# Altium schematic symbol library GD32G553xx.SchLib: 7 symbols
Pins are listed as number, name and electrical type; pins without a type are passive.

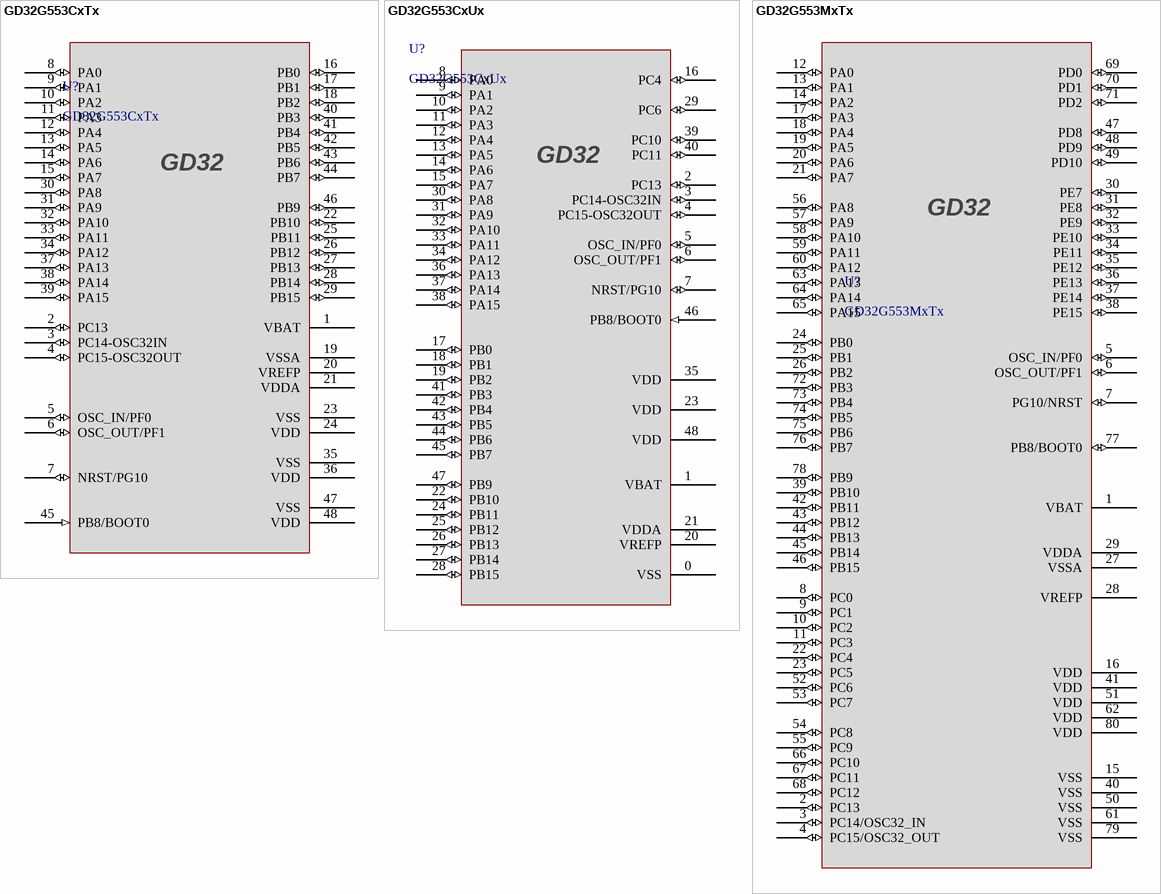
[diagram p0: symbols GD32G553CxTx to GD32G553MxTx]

## GD32G553CxTx
designator U?
footprint LQFP48_7x7x1.6
pins: 1 VBAT (power), 2 PC13 (io), 3 PC14-OSC32IN (io), 4 PC15-OSC32OUT (io), 5 OSC_IN/PF0 (io), 6 OSC_OUT/PF1 (io), 7 NRST/PG10 (io), 8 PA0 (io), 9 PA1 (io), 10 PA2 (io), 11 PA3 (io), 12 PA4 (io), 13 PA5 (io), 14 PA6 (io), 15 PA7 (io), 16 PB0 (io), 17 PB1 (io), 18 PB2 (io), 19 VSSA (power), 20 VREFP (power), 21 VDDA (power), 22 PB10 (io), 23 VSS (power), 24 VDD (power), 25 PB11 (io), 26 PB12 (io), 27 PB13 (io), 28 PB14 (io), 29 PB15 (io), 30 PA8 (io), 31 PA9 (io), 32 PA10 (io), 33 PA11 (io), 34 PA12 (io), 35 VSS (power), 36 VDD (power), 37 PA13 (io), 38 PA14 (io), 39 PA15 (io), 40 PB3 (io), 41 PB4 (io), 42 PB5 (io), 43 PB6 (io), 44 PB7 (io), 45 PB8/BOOT0 (in), 46 PB9 (io), 47 VSS (power), 48 VDD (power)

## GD32G553CxUx
designator U?
footprint QFN48_7X7X0.6
pins: 0 VSS (power), 1 VBAT (power), 2 PC13 (io), 3 PC14-OSC32IN (io), 4 PC15-OSC32OUT (io), 5 OSC_IN/PF0 (io), 6 OSC_OUT/PF1 (io), 7 NRST/PG10 (io), 8 PA0 (io), 9 PA1 (io), 10 PA2 (io), 11 PA3 (io), 12 PA4 (io), 13 PA5 (io), 14 PA6 (io), 15 PA7 (io), 16 PC4 (io), 17 PB0 (io), 18 PB1 (io), 19 PB2 (io), 20 VREFP (power), 21 VDDA (power), 22 PB10 (io), 23 VDD (power), 24 PB11 (io), 25 PB12 (io), 26 PB13 (io), 27 PB14 (io), 28 PB15 (io), 29 PC6 (io), 30 PA8 (io), 31 PA9 (io), 32 PA10 (io), 33 PA11 (io), 34 PA12 (io), 35 VDD (power), 36 PA13 (io), 37 PA14 (io), 38 PA15 (io), 39 PC10 (io), 40 PC11 (io), 41 PB3 (io), 42 PB4 (io), 43 PB5 (io), 44 PB6 (io), 45 PB7 (io), 46 PB8/BOOT0 (in), 47 PB9 (io), 48 VDD (power)

## GD32G553MxTx
designator U?
footprint LQFP80_12x12x1.6
pins: 1 VBAT (power), 2 PC13 (io), 3 PC14/OSC32_IN (io), 4 PC15/OSC32_OUT (io), 5 OSC_IN/PF0 (io), 6 OSC_OUT/PF1 (io), 7 PG10/NRST (io), 8 PC0 (io), 9 PC1 (io), 10 PC2 (io), 11 PC3 (io), 12 PA0 (io), 13 PA1 (io), 14 PA2 (io), 15 VSS (power), 16 VDD (power), 17 PA3 (io), 18 PA4 (io), 19 PA5 (io), 20 PA6 (io), 21 PA7 (io), 22 PC4 (io), 23 PC5 (io), 24 PB0 (io), 25 PB1 (io), 26 PB2 (io), 27 VSSA (power), 28 VREFP (power), 29 VDDA (power), 30 PE7 (io), 31 PE8 (io), 32 PE9 (io), 33 PE10 (io), 34 PE11 (io), 35 PE12 (io), 36 PE13 (io), 37 PE14 (io), 38 PE15 (io), 39 PB10 (io), 40 VSS (power), 41 VDD (power), 42 PB11 (io), 43 PB12 (io), 44 PB13 (io), 45 PB14 (io), 46 PB15 (io), 47 PD8 (io), 48 PD9 (io), 49 PD10 (io), 50 VSS (power), 51 VDD (power), 52 PC6 (io), 53 PC7 (io), 54 PC8 (io), 55 PC9 (io), 56 PA8 (io), 57 PA9 (io), 58 PA10 (io), 59 PA11 (io), 60 PA12 (io), 61 VSS (power), 62 VDD (power), 63 PA13 (io), 64 PA14 (io), 65 PA15 (io), 66 PC10 (io), 67 PC11 (io), 68 PC12 (io), 69 PD0 (io), 70 PD1 (io), 71 PD2 (io), 72 PB3 (io), 73 PB4 (io), 74 PB5 (io), 75 PB6 (io), 76 PB7 (io), 77 PB8/BOOT0 (io), 78 PB9 (io), 79 VSS (power), 80 VDD (power)

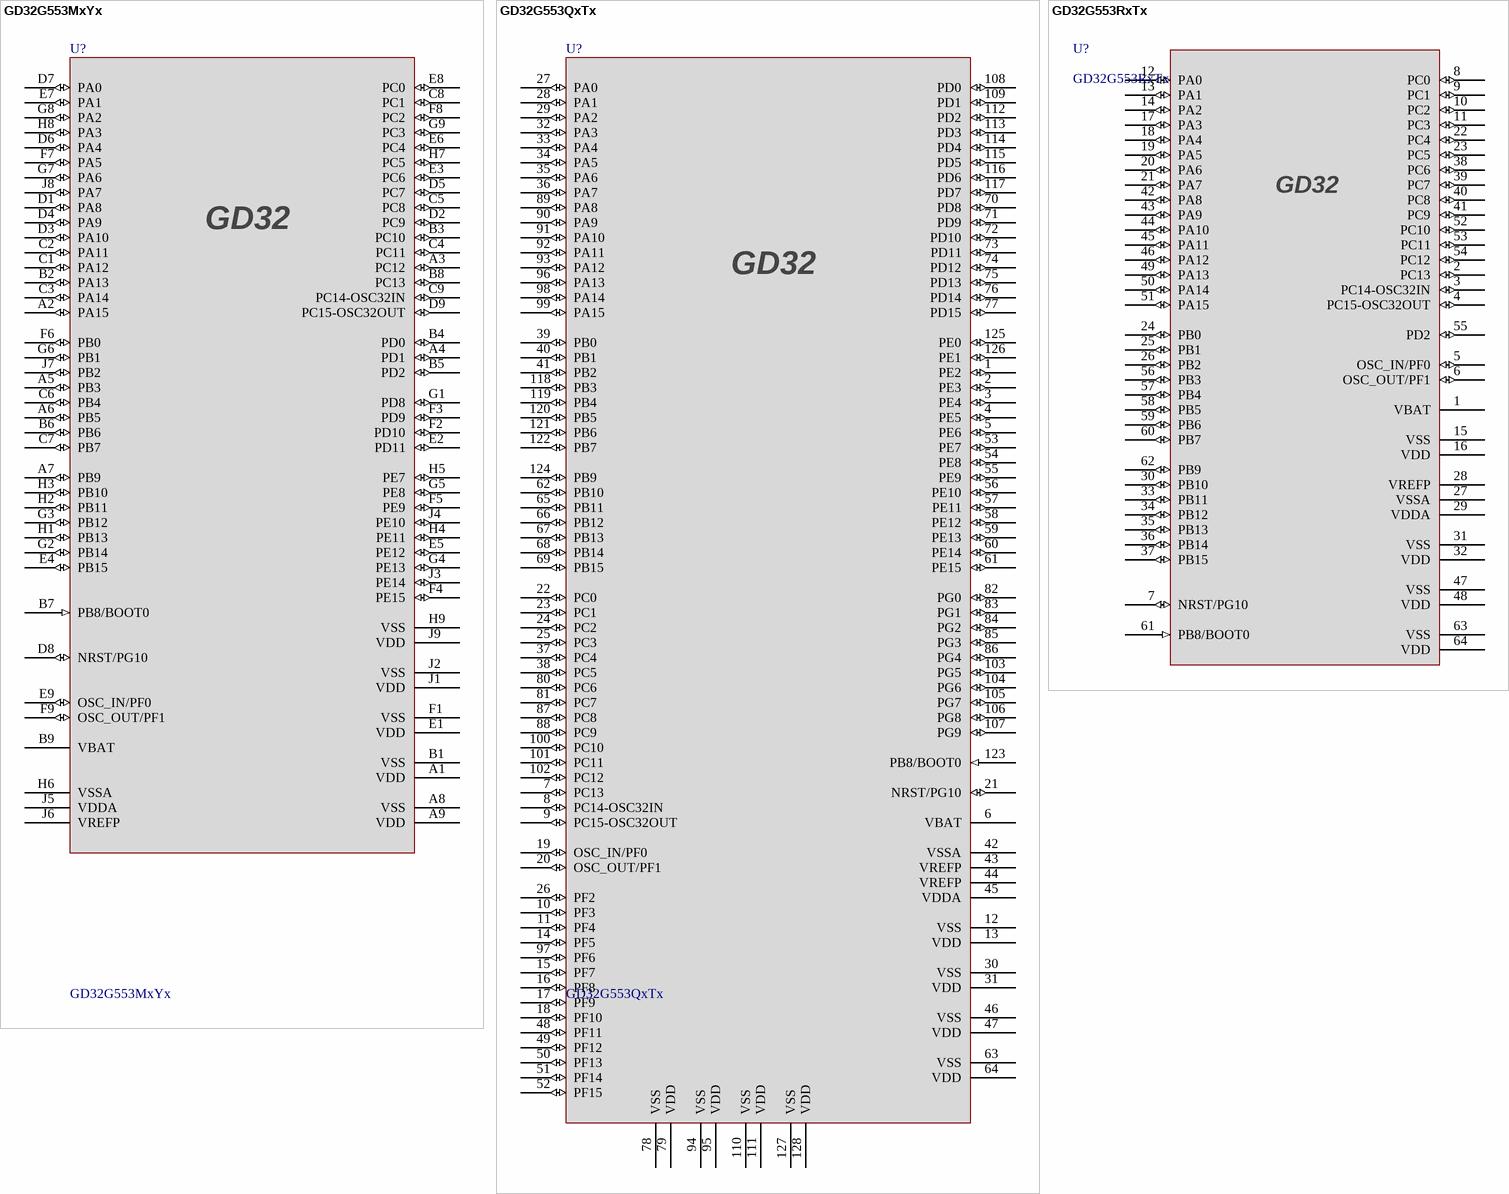
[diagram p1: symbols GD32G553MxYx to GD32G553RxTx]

## GD32G553MxYx
designator U?
footprint WLCSP81_4x4x0.58
pins: A1 VDD (power), A2 PA15 (io), A3 PC12 (io), A4 PD1 (io), A5 PB3 (io), A6 PB5 (io), A7 PB9 (io), A8 VSS (power), A9 VDD (power), B1 VSS (power), B2 PA13 (io), B3 PC10 (io), B4 PD0 (io), B5 PD2 (io), B6 PB6 (io), B7 PB8/BOOT0 (in), B8 PC13 (io), B9 VBAT (power), C1 PA12 (io), C2 PA11 (io), C3 PA14 (io), C4 PC11 (io), C5 PC8 (io), C6 PB4 (io), C7 PB7 (io), C8 PC1 (io), C9 PC14-OSC32IN (io), D1 PA8 (io), D2 PC9 (io), D3 PA10 (io), D4 PA9 (io), D5 PC7 (io), D6 PA4 (io), D7 PA0 (io), D8 NRST/PG10 (io), D9 PC15-OSC32OUT (io), E1 VDD (power), E2 PD11 (io), E3 PC6 (io), E4 PB15 (io), E5 PE12 (io), E6 PC4 (io), E7 PA1 (io), E8 PC0 (io), E9 OSC_IN/PF0 (io), F1 VSS (power), F2 PD10 (io), F3 PD9 (io), F4 PE15 (io), F5 PE9 (io), F6 PB0 (io), F7 PA5 (io), F8 PC2 (io), F9 OSC_OUT/PF1 (io), G1 PD8 (io), G2 PB14 (io), G3 PB12 (io), G4 PE13 (io), G5 PE8 (io), G6 PB1 (io), G7 PA6 (io), G8 PA2 (io), G9 PC3 (io), H1 PB13 (io), H2 PB11 (io), H3 PB10 (io), H4 PE11 (io), H5 PE7 (io), H6 VSSA (power), H7 PC5 (io), H8 PA3 (io), H9 VSS (power), J1 VDD (power), J2 VSS (power), J3 PE14 (io), J4 PE10 (io), J5 VDDA (power), J6 VREFP (power), J7 PB2 (io), J8 PA7 (io), J9 VDD (power)
2 alternate drawings of the same symbol

## GD32G553QxTx
designator U?
footprint LQFP128_14X14X1.6
pins: 1 PE2 (io), 2 PE3 (io), 3 PE4 (io), 4 PE5 (io), 5 PE6 (io), 6 VBAT (power), 7 PC13 (io), 8 PC14-OSC32IN (io), 9 PC15-OSC32OUT (io), 10 PF3 (io), 11 PF4 (io), 12 VSS (power), 13 VDD (power), 14 PF5 (io), 15 PF7 (io), 16 PF8 (io), 17 PF9 (io), 18 PF10 (io), 19 OSC_IN/PF0 (io), 20 OSC_OUT/PF1 (io), 21 NRST/PG10 (io), 22 PC0 (io), 23 PC1 (io), 24 PC2 (io), 25 PC3 (io), 26 PF2 (io), 27 PA0 (io), 28 PA1 (io), 29 PA2 (io), 30 VSS (power), 31 VDD (power), 32 PA3 (io), 33 PA4 (io), 34 PA5 (io), 35 PA6 (io), 36 PA7 (io), 37 PC4 (io), 38 PC5 (io), 39 PB0 (io), 40 PB1 (io), 41 PB2 (io), 42 VSSA (power), 43 VREFP (power), 44 VREFP (power), 45 VDDA (power), 46 VSS (power), 47 VDD (power), 48 PF11 (io), 49 PF12 (io), 50 PF13 (io), 51 PF14 (io), 52 PF15 (io), 53 PE7 (io), 54 PE8 (io), 55 PE9 (io), 56 PE10 (io), 57 PE11 (io), 58 PE12 (io), 59 PE13 (io), 60 PE14 (io), 61 PE15 (io), 62 PB10 (io), 63 VSS (power), 64 VDD (power), 65 PB11 (io), 66 PB12 (io), 67 PB13 (io), 68 PB14 (io), 69 PB15 (io), 70 PD8 (io), 71 PD9 (io), 72 PD10 (io), 73 PD11 (io), 74 PD12 (io), 75 PD13 (io), 76 PD14 (io), 77 PD15 (io), 78 VSS (power), 79 VDD (power), 80 PC6 (io), 81 PC7 (io), 82 PG0 (io), 83 PG1 (io), 84 PG2 (io), 85 PG3 (io), 86 PG4 (io), 87 PC8 (io), 88 PC9 (io), 89 PA8 (io), 90 PA9 (io), 91 PA10 (io), 92 PA11 (io), 93 PA12 (io), 94 VSS (power), 95 VDD (power), 96 PA13 (io), 97 PF6 (io), 98 PA14 (io), 99 PA15 (io), 100 PC10 (io), 101 PC11 (io), 102 PC12 (io), 103 PG5 (io), 104 PG6 (io), 105 PG7 (io), 106 PG8 (io), 107 PG9 (io), 108 PD0 (io), 109 PD1 (io), 110 VSS (power), 111 VDD (power), 112 PD2 (io), 113 PD3 (io), 114 PD4 (io), 115 PD5 (io), 116 PD6 (io), 117 PD7 (io), 118 PB3 (io), 119 PB4 (io), 120 PB5 (io), 121 PB6 (io), 122 PB7 (io), 123 PB8/BOOT0 (in), 124 PB9 (io), 125 PE0 (io), 126 PE1 (io), 127 VSS (power), 128 VDD (power)
2 alternate drawings of the same symbol

## GD32G553RxTx
designator U?
footprint LQPF64_10x10x1.6
pins: 1 VBAT (power), 2 PC13 (io), 3 PC14-OSC32IN (io), 4 PC15-OSC32OUT (io), 5 OSC_IN/PF0 (io), 6 OSC_OUT/PF1 (io), 7 NRST/PG10 (io), 8 PC0 (io), 9 PC1 (io), 10 PC2 (io), 11 PC3 (io), 12 PA0 (io), 13 PA1 (io), 14 PA2 (io), 15 VSS (power), 16 VDD (power), 17 PA3 (io), 18 PA4 (io), 19 PA5 (io), 20 PA6 (io), 21 PA7 (io), 22 PC4 (io), 23 PC5 (io), 24 PB0 (io), 25 PB1 (io), 26 PB2 (io), 27 VSSA (power), 28 VREFP (power), 29 VDDA (power), 30 PB10 (io), 31 VSS (power), 32 VDD (power), 33 PB11 (io), 34 PB12 (io), 35 PB13 (io), 36 PB14 (io), 37 PB15 (io), 38 PC6 (io), 39 PC7 (io), 40 PC8 (io), 41 PC9 (io), 42 PA8 (io), 43 PA9 (io), 44 PA10 (io), 45 PA11 (io), 46 PA12 (io), 47 VSS (power), 48 VDD (power), 49 PA13 (io), 50 PA14 (io), 51 PA15 (io), 52 PC10 (io), 53 PC11 (io), 54 PC12 (io), 55 PD2 (io), 56 PB3 (io), 57 PB4 (io), 58 PB5 (io), 59 PB6 (io), 60 PB7 (io), 61 PB8/BOOT0 (in), 62 PB9 (io), 63 VSS (power), 64 VDD (power)

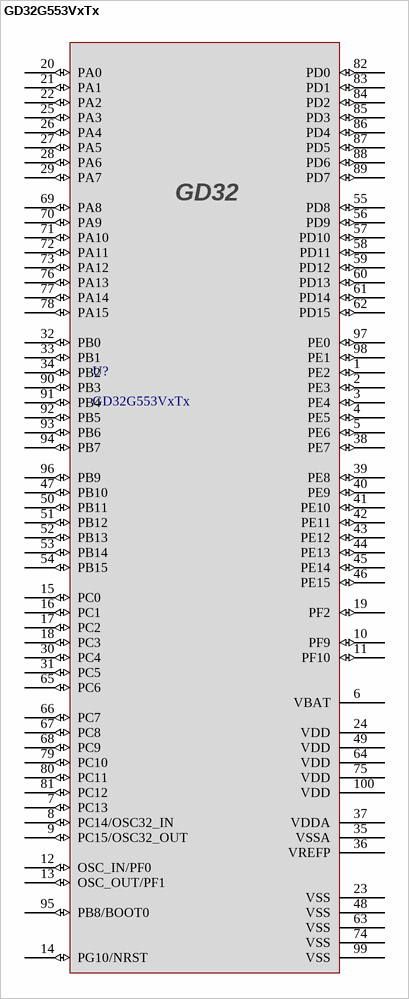
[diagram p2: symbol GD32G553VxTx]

## GD32G553VxTx
designator U?
footprint LQFP100_14x14x1.6
pins: 1 PE2 (io), 2 PE3 (io), 3 PE4 (io), 4 PE5 (io), 5 PE6 (io), 6 VBAT (power), 7 PC13 (io), 8 PC14/OSC32_IN (io), 9 PC15/OSC32_OUT (io), 10 PF9 (io), 11 PF10 (io), 12 OSC_IN/PF0 (io), 13 OSC_OUT/PF1 (io), 14 PG10/NRST (io), 15 PC0 (io), 16 PC1 (io), 17 PC2 (io), 18 PC3 (io), 19 PF2 (io), 20 PA0 (io), 21 PA1 (io), 22 PA2 (io), 23 VSS (power), 24 VDD (power), 25 PA3 (io), 26 PA4 (io), 27 PA5 (io), 28 PA6 (io), 29 PA7 (io), 30 PC4 (io), 31 PC5 (io), 32 PB0 (io), 33 PB1 (io), 34 PB2 (io), 35 VSSA (power), 36 VREFP (power), 37 VDDA (power), 38 PE7 (io), 39 PE8 (io), 40 PE9 (io), 41 PE10 (io), 42 PE11 (io), 43 PE12 (io), 44 PE13 (io), 45 PE14 (io), 46 PE15 (io), 47 PB10 (io), 48 VSS (power), 49 VDD (power), 50 PB11 (io), 51 PB12 (io), 52 PB13 (io), 53 PB14 (io), 54 PB15 (io), 55 PD8 (io), 56 PD9 (io), 57 PD10 (io), 58 PD11 (io), 59 PD12 (io), 60 PD13 (io), 61 PD14 (io), 62 PD15 (io), 63 VSS (power), 64 VDD (power), 65 PC6 (io), 66 PC7 (io), 67 PC8 (io), 68 PC9 (io), 69 PA8 (io), 70 PA9 (io), 71 PA10 (io), 72 PA11 (io), 73 PA12 (io), 74 VSS (power), 75 VDD (power), 76 PA13 (io), 77 PA14 (io), 78 PA15 (io), 79 PC10 (io), 80 PC11 (io), 81 PC12 (io), 82 PD0 (io), 83 PD1 (io), 84 PD2 (io), 85 PD3 (io), 86 PD4 (io), 87 PD5 (io), 88 PD6 (io), 89 PD7 (io), 90 PB3 (io), 91 PB4 (io), 92 PB5 (io), 93 PB6 (io), 94 PB7 (io), 95 PB8/BOOT0 (io), 96 PB9 (io), 97 PE0 (io), 98 PE1 (io), 99 VSS (power), 100 VDD (power)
